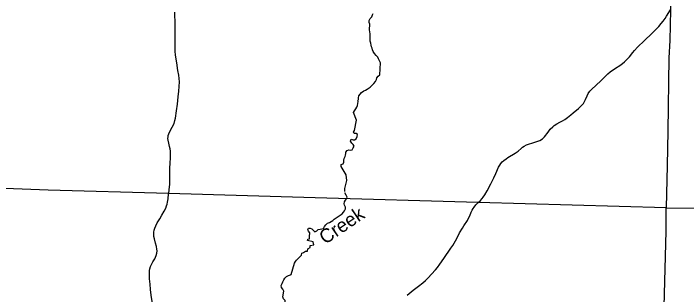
# Model space of a CAD drawing. Extents: x -6.3 to 34, y 0 to 22.
# Drawn here: x 5.581 to 8.74, y 16.554 to 17.873 of the extents above; entities that cross this region are included whole.
import ezdxf

# ---------------------------------------------------------------- set-up
doc = ezdxf.new("R2010")
doc.units = 0
for name, color, linetype in [('GM_X_Minor_River', 7, 'Continuous'), ('GM_X_Minor_River_Text', 7, 'Continuous'), ('GM_X_State_Route', 7, 'Continuous'), ('GM_X_Township', 7, 'Continuous')]:
    doc.layers.add(name, color=color, linetype=linetype)

msp = doc.modelspace()

# ---------------------------------------------------------------- linework, layer by layer
at = {"layer": 'GM_X_Minor_River'}
for points in [[(7.1975, 17.463), (7.1996, 17.4693), (7.2009, 17.4777), (7.2026, 17.4858), (7.2086, 17.4944), (7.215, 17.5017), (7.2248, 17.5091), (7.2339, 17.5135), (7.2417, 17.517), (7.2551, 17.5264), (7.2634, 17.5353), (7.2724, 17.545), (7.2804, 17.5532), (7.284, 17.5628), (7.286, 17.5714), (7.2925, 17.5782), (7.3005, 17.5845), (7.3029, 17.6416), (7.299, 17.6507), (7.2948, 17.6603), (7.2903, 17.6673), (7.283, 17.6764), (7.2748, 17.6857), (7.2696, 17.6943), (7.2654, 17.7029), (7.2638, 17.7096), (7.2616, 17.7161), (7.2598, 17.7242), (7.2576, 17.7338), (7.2557, 17.7434), (7.2552, 17.7507), (7.2551, 17.7643), (7.2545, 17.7778), (7.2528, 17.7867), (7.2517, 17.7955), (7.2531, 17.8221), (7.2507, 17.8312), (7.2496, 17.84), (7.2553, 17.8487), (7.2622, 17.8571), (7.2666, 17.8659), (7.2688, 17.8729)], [(7.136, 17.0373), (7.1365, 17.0423), (7.1365, 17.0511), (7.1456, 17.0897), (7.1428, 17.115), (7.1189, 17.1552), (7.1188, 17.1638), (7.1279, 17.1678), (7.132, 17.1748), (7.1314, 17.1839), (7.1334, 17.1923), (7.1383, 17.2014), (7.1393, 17.2085), (7.1405, 17.216), (7.1413, 17.2225), (7.1464, 17.2301), (7.1547, 17.2328), (7.1615, 17.2318), (7.1703, 17.2326), (7.176, 17.2418), (7.1798, 17.2501), (7.1756, 17.2582), (7.1688, 17.2641), (7.1628, 17.2735), (7.1666, 17.2824), (7.1752, 17.2803), (7.182, 17.2793), (7.19, 17.2848), (7.1946, 17.2955), (7.1963, 17.3044), (7.1895, 17.3091), (7.1802, 17.309), (7.1773, 17.3155), (7.1814, 17.3239), (7.1902, 17.3721), (7.1772, 17.4075), (7.1808, 17.4155), (7.1885, 17.425), (7.1921, 17.4336), (7.1951, 17.4414), (7.1977, 17.4508), (7.1984, 17.4592), (7.1975, 17.463)], [(6.8845, 16.6476), (6.9001, 16.7017), (6.905, 16.709), (6.9091, 16.7155), (6.9171, 16.7236), (6.9251, 16.7306), (6.9324, 16.7385), (6.9341, 16.7473), (6.9429, 16.7507), (6.9515, 16.7567), (6.9605, 16.7575), (6.9631, 16.7679), (6.9729, 16.7739), (6.9737, 16.7846), (6.9908, 16.7865), (6.9876, 16.8018), (6.9616, 16.808), (6.9621, 16.8137), (6.9709, 16.8155), (6.9698, 16.8265), (6.9711, 16.8429), (6.9653, 16.8512), (6.963, 16.8577), (6.9655, 16.8647), (6.9733, 16.8652), (6.9808, 16.8629), (6.9892, 16.8551), (6.9957, 16.8486), (7.0045, 16.8533), (7.0112, 16.8586), (7.0198, 16.8612), (7.0288, 16.8617), (7.0356, 16.8643), (7.0407, 16.8727), (7.0464, 16.8815), (7.0554, 16.8886), (7.0642, 16.892), (7.0723, 16.8967), (7.0792, 16.9009), (7.0867, 16.9071), (7.0953, 16.9131), (7.1051, 16.9197), (7.1144, 16.927), (7.1229, 16.9332), (7.1302, 16.94), (7.1348, 16.9473), (7.1387, 16.9554), (7.1386, 16.9645), (7.1344, 16.9731), (7.1334, 16.9798), (7.1349, 16.9884), (7.1387, 16.9962), (7.1442, 17.003), (7.147, 17.0116), (7.1428, 17.0207), (7.1364, 17.0316)], [(6.8409, 16.5004), (6.8567, 16.517), (6.8559, 16.5258), (6.8484, 16.5338), (6.8457, 16.5429), (6.85, 16.5697), (6.8453, 16.5785), (6.8393, 16.5868), (6.8372, 16.5959), (6.8421, 16.6053), (6.8447, 16.6131), (6.8501, 16.6222), (6.855, 16.6305), (6.8625, 16.6386), (6.8715, 16.6436), (6.8809, 16.647), (6.8845, 16.6476)]]:
    msp.add_lwpolyline(points, dxfattribs=at)
at = {"layer": 'GM_X_State_Route'}
for points in [[(8.5767, 17.7786), (8.5945, 17.796), (8.6098, 17.8117), (8.6216, 17.8254), (8.63, 17.8364), (8.6391, 17.8494), (8.6458, 17.8596), (8.6642, 17.8894)], [(6.3094, 17.0278), (6.3114, 17.0445), (6.3142, 17.0725), (6.3148, 17.093), (6.3149, 17.145), (6.3161, 17.1714), (6.3173, 17.1932), (6.3179, 17.2086), (6.3179, 17.2171), (6.3173, 17.2265), (6.3158, 17.2375), (6.3136, 17.249), (6.3095, 17.2639), (6.3066, 17.278), (6.3057, 17.2863), (6.3063, 17.2934), (6.3074, 17.2996), (6.3103, 17.3076), (6.3137, 17.3155), (6.3259, 17.3386), (6.3344, 17.3567), (6.3385, 17.3699), (6.3414, 17.382), (6.3468, 17.4162), (6.3504, 17.4471), (6.354, 17.4816), (6.3571, 17.5083), (6.3587, 17.5302), (6.3599, 17.5525), (6.359, 17.5682), (6.3569, 17.5826), (6.3531, 17.6056), (6.347, 17.6415), (6.3417, 17.6769), (6.34, 17.6953), (6.3394, 17.7145), (6.3397, 17.7722), (6.3401, 17.8036), (6.3394, 17.8361), (6.3383, 17.8622), (6.3375, 17.8788)], [(7.8037, 17.0411), (7.8218, 17.0742), (7.835, 17.1016), (7.8445, 17.1225), (7.858, 17.1509), (7.8637, 17.1614), (7.8682, 17.1681), (7.8751, 17.1761), (7.8826, 17.1834), (7.8926, 17.1909), (7.9019, 17.1974), (7.935, 17.2171), (7.949, 17.2264), (7.9638, 17.2397), (7.97, 17.2452), (7.978, 17.2507), (7.989, 17.2564), (7.9989, 17.2603), (8.0181, 17.2659), (8.042, 17.2732), (8.0521, 17.2775), (8.0645, 17.285), (8.0735, 17.2943), (8.0898, 17.316), (8.1006, 17.3295), (8.1117, 17.3404), (8.1191, 17.3468), (8.1318, 17.3553), (8.1456, 17.3623), (8.1578, 17.3689), (8.169, 17.3759), (8.1809, 17.3851), (8.1966, 17.3977), (8.2086, 17.4073), (8.2321, 17.4269), (8.2474, 17.4408), (8.256, 17.4511), (8.2611, 17.4591), (8.266, 17.4688), (8.273, 17.4859), (8.278, 17.4971), (8.2857, 17.5081), (8.2932, 17.5166), (8.3374, 17.5561), (8.3559, 17.5749), (8.3702, 17.5896), (8.3818, 17.5994), (8.4018, 17.613), (8.4317, 17.6323), (8.4492, 17.6462), (8.4604, 17.6565), (8.472, 17.6696), (8.4884, 17.6905), (8.495, 17.6984), (8.5103, 17.7149), (8.5424, 17.7468), (8.5767, 17.7786)], [(6.2241, 16.578), (6.2219, 16.6021), (6.22, 16.6272), (6.2193, 16.6502), (6.22, 16.6661), (6.2211, 16.6745), (6.2245, 16.6857), (6.2289, 16.695), (6.2353, 16.7068), (6.2438, 16.722), (6.2507, 16.7373), (6.2531, 16.7474), (6.2547, 16.7589), (6.2544, 16.7676), (6.2525, 16.7789), (6.2479, 16.7944), (6.2421, 16.8148), (6.2401, 16.8263), (6.2395, 16.8356), (6.2401, 16.847), (6.2416, 16.856), (6.2441, 16.8661), (6.2489, 16.877), (6.2561, 16.8902), (6.2671, 16.9093), (6.2775, 16.9268), (6.2883, 16.9455), (6.296, 16.9598), (6.2999, 16.97), (6.3021, 16.9783), (6.3036, 16.9867), (6.3063, 17.0036), (6.3093, 17.0271), (6.3094, 17.0278)], [(7.428, 16.5517), (7.4562, 16.5737), (7.4821, 16.5939), (7.5017, 16.609), (7.5145, 16.62), (7.5275, 16.6323), (7.5436, 16.6493), (7.5614, 16.6692), (7.5714, 16.6813), (7.5828, 16.6967), (7.6007, 16.7234), (7.6342, 16.7715), (7.6434, 16.7846), (7.6562, 16.8064), (7.6674, 16.8293), (7.6746, 16.8438), (7.6877, 16.8658), (7.695, 16.8764), (7.7119, 16.9019), (7.7173, 16.9122), (7.7229, 16.9232), (7.7297, 16.9402), (7.7342, 16.95), (7.7385, 16.958), (7.7432, 16.9647), (7.7506, 16.9742), (7.7617, 16.9853), (7.7725, 16.9958), (7.7801, 17.0042), (7.7857, 17.0112), (7.7928, 17.022), (7.8037, 17.0411)], [(6.2994, 16.2569), (6.3007, 16.2643), (6.3022, 16.2816), (6.3008, 16.2907), (6.2977, 16.2994), (6.2916, 16.3097), (6.2822, 16.3206), (6.2748, 16.3289), (6.2686, 16.3367), (6.2614, 16.3539), (6.2585, 16.3654), (6.2546, 16.3846), (6.249, 16.4143), (6.2386, 16.4839), (6.2277, 16.5508), (6.2241, 16.578)]]:
    msp.add_lwpolyline(points, dxfattribs=at)
at = {"layer": 'GM_X_Township'}
for points in [[(8.712, 20.4444), (8.7081, 20.1879), (8.7029, 19.9815), (8.6792, 19.0514), (8.6791, 18.5896), (8.6708, 18.3533), (8.664, 17.8898), (8.6619, 17.7454), (8.6569, 17.6641), (8.6519, 17.32), (8.6486, 17.1596), (8.6445, 16.9602), (7.7616, 16.9856), (6.9974, 17.0077), (6.3091, 17.0275), (5.744, 17.0438), (5.416, 17.0563)], [(8.5851, 14.1737), (8.5926, 14.4543), (8.601, 14.8469), (8.6015, 14.8772), (8.6108, 15.419), (8.6117, 15.4701), (8.6133, 15.5687), (8.627, 16.0919), (8.6276, 16.23), (8.6289, 16.2623), (8.6446, 16.8511), (8.6445, 16.9602), (8.9341, 16.9598)]]:
    msp.add_lwpolyline(points, dxfattribs=at)

# ---------------------------------------------------------------- texts
at = {"layer": 'GM_X_Minor_River_Text'}
msp.add_text('Creek', height=0.0649, rotation=34.207, dxfattribs=at).set_placement((7.0437, 16.7867))

doc.saveas('drawing.dxf')
